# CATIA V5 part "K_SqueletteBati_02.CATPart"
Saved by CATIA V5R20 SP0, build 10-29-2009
Part number: Squelette_bati_02
Publications: "Plan_ref_02", "Droite.4", "Droite.3", "Droite.2", "Droite.1"
Bounding box of the stored display mesh (mm): x -250 to 0, y -40 to 40, z -180 to 180
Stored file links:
  G:\Khaled_CFAO_2011\ST2M\ST2M_GR2\jcoetard\Khaled\CAD_CATIA\K_SqueletteBati_02.CATPart
  G:\Khaled_CFAO_2011\ST2M\ST2M_GR2\jcoetard\Khaled\CAD_CATIA\K_Squelette.CATProduct
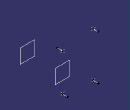
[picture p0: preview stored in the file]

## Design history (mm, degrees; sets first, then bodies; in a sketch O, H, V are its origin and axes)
Set1
  Plane1 "Plan_Ref": linked copy from another document
  Point1 to Point3: linked copy from another document
  Point4 "Point.8": linked copy from another document
Set2 "Set géométrique"
  Plane2 "Plan_ref_02": type Offset, RefPlane Plane1, Offset -284.606
  Line1: type Normal, RefPoint Point1, RefSkin Plane2, Start 0, End 40
  Line2: type Normal, RefPoint Point2, RefSkin Plane2, Start 0, End 40
  Line3: type Normal, RefPoint Point3, RefSkin Plane2, Start 0, End 40
  Line4: type Normal, RefPoint Point4, RefSkin Plane2, Start 0, End 40
Body1 (main body)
